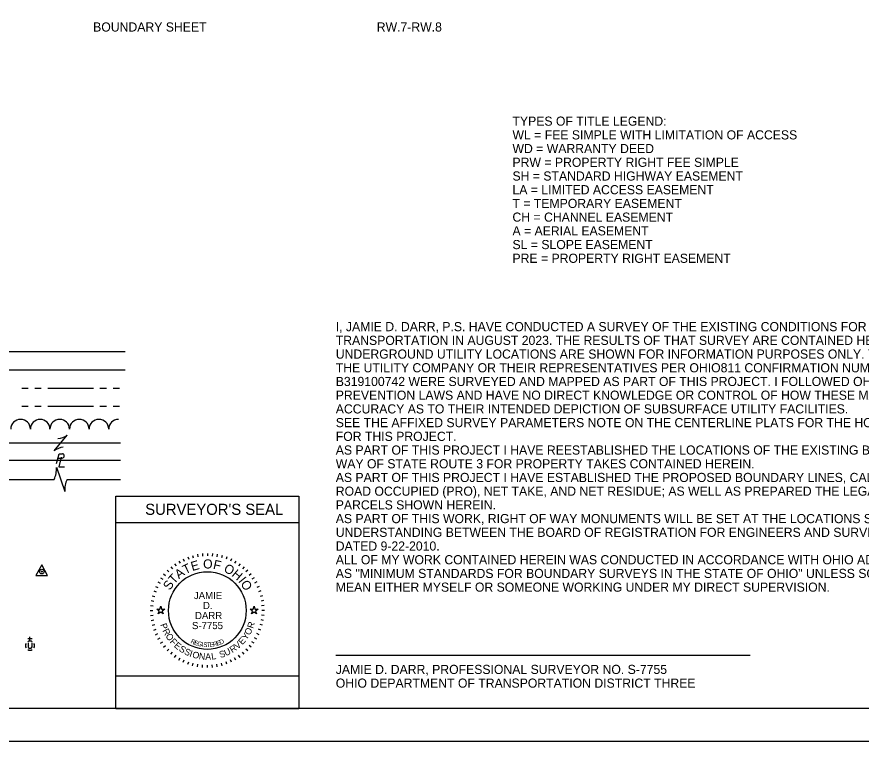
# Model space of a CAD drawing. Extents: x 0 to 34, y 0 to 22.
# Drawn here: x 12.52 to 25.46, y 0 to 11.09 of the extents above; entities that cross this region are included whole.
import ezdxf

# ---------------------------------------------------------------- set-up
doc = ezdxf.new("R2010")
doc.units = 0
for name, color, linetype in [('Default', 7, 'Continuous'), ('SH_Border', 7, 'Continuous'), ('SH_Cut_Line', 7, 'Continuous'), ('SH_Data', 7, 'Continuous'), ('SH_Text', 7, 'Continuous')]:
    doc.layers.add(name, color=color, linetype=linetype)

msp = doc.modelspace()

# ---------------------------------------------------------------- linework, layer by layer
at = {"layer": 'Default'}
msp.add_line((17.41, 1.318), (23.762, 1.318), dxfattribs=at)
for points in [[(14.666, 2.02), (14.713, 2.02), (14.727, 2.065), (14.742, 2.02), (14.789, 2.02), (14.751, 1.992), (14.765, 1.948), (14.727, 1.975), (14.689, 1.948), (14.704, 1.992)], [(16.096, 2.02), (16.143, 2.02), (16.157, 2.065), (16.172, 2.02), (16.219, 2.02), (16.181, 1.992), (16.195, 1.948), (16.157, 1.975), (16.119, 1.948), (16.134, 1.992)]]:
    msp.add_lwpolyline(points, close=True, dxfattribs=at)
at = {"layer": 'SH_Border'}
msp.add_lwpolyline([(1.5, 21.5), (33.5, 21.5), (33.5, 0.5), (1.5, 0.5)], close=True, dxfattribs=at)
at = {"layer": 'SH_Cut_Line'}
msp.add_lwpolyline([(0, 0), (34, 0), (34, 22), (0, 22)], close=True, dxfattribs=at)
at = {"layer": 'SH_Data'}
for p, q in [((14.042, 0.5), (14.042, 3.75)), ((14.042, 3.75), (16.842, 3.75)), ((16.842, 3.75), (16.842, 0.5)), ((14.042, 3.35), (16.842, 3.35)), ((15.29, 2.862), (15.297, 2.822)), ((15.366, 2.872), (15.369, 2.832)), ((15.442, 2.875), (15.442, 2.835)), ((15.519, 2.872), (15.515, 2.832)), ((15.594, 2.862), (15.587, 2.822)), ((15.005, 2.758), (15.025, 2.723)), ((15.072, 2.793), (15.089, 2.757)), ((15.143, 2.822), (15.157, 2.785)), ((15.216, 2.845), (15.226, 2.807)), ((15.669, 2.845), (15.658, 2.807)), ((15.742, 2.822), (15.728, 2.785)), ((15.812, 2.793), (15.795, 2.757)), ((15.88, 2.758), (15.86, 2.723)), ((14.824, 2.619), (14.852, 2.59)), ((14.88, 2.67), (14.906, 2.64)), ((14.94, 2.717), (14.963, 2.684)), ((15.944, 2.717), (15.921, 2.684)), ((16.005, 2.67), (15.979, 2.64)), ((16.061, 2.619), (16.033, 2.59)), ((14.725, 2.502), (14.758, 2.479)), ((14.772, 2.562), (14.803, 2.537)), ((16.113, 2.562), (16.082, 2.537)), ((16.159, 2.502), (16.126, 2.479)), ((14.649, 2.37), (14.685, 2.353)), ((14.684, 2.438), (14.719, 2.418)), ((16.2, 2.438), (16.165, 2.418)), ((16.235, 2.37), (16.199, 2.353)), ((14.597, 2.226), (14.636, 2.216)), ((14.62, 2.299), (14.658, 2.286)), ((16.264, 2.299), (16.227, 2.286)), ((16.287, 2.226), (16.249, 2.216)), ((14.571, 2.076), (14.61, 2.073)), ((14.581, 2.152), (14.62, 2.145)), ((16.304, 2.152), (16.265, 2.145)), ((16.314, 2.076), (16.274, 2.073)), ((14.567, 2), (14.607, 2)), ((16.317, 2), (16.277, 2)), ((14.571, 1.924), (14.61, 1.927)), ((14.581, 1.848), (14.62, 1.855)), ((16.304, 1.848), (16.265, 1.855)), ((16.314, 1.924), (16.274, 1.927)), ((14.597, 1.774), (14.636, 1.784)), ((14.62, 1.701), (14.658, 1.714)), ((16.264, 1.701), (16.227, 1.714)), ((16.287, 1.774), (16.249, 1.784)), ((14.649, 1.63), (14.685, 1.647)), ((14.684, 1.563), (14.719, 1.583)), ((16.2, 1.563), (16.165, 1.583)), ((16.235, 1.63), (16.199, 1.647)), ((14.725, 1.498), (14.758, 1.521)), ((14.772, 1.438), (14.803, 1.463)), ((16.113, 1.438), (16.082, 1.463)), ((16.159, 1.498), (16.126, 1.521)), ((14.824, 1.381), (14.852, 1.41)), ((14.88, 1.33), (14.906, 1.36)), ((14.94, 1.283), (14.963, 1.316)), ((15.944, 1.283), (15.921, 1.316)), ((16.005, 1.33), (15.979, 1.36)), ((16.061, 1.381), (16.033, 1.41)), ((15.005, 1.242), (15.025, 1.277)), ((15.072, 1.207), (15.089, 1.243)), ((15.143, 1.178), (15.157, 1.215)), ((15.216, 1.155), (15.226, 1.193)), ((15.29, 1.138), (15.297, 1.178)), ((15.366, 1.128), (15.369, 1.168)), ((15.442, 1.125), (15.442, 1.165)), ((15.519, 1.128), (15.515, 1.168)), ((15.594, 1.138), (15.587, 1.178)), ((15.669, 1.155), (15.658, 1.193)), ((15.742, 1.178), (15.728, 1.215)), ((15.812, 1.207), (15.795, 1.243)), ((15.88, 1.242), (15.86, 1.277)), ((14.042, 0.5), (16.842, 0.5))]:
    msp.add_line(p, q, dxfattribs=at)
msp.add_lwpolyline([(14.042, 0.5), (14.042, 1), (16.842, 1), (16.842, 0.5)], close=True, dxfattribs=at)
msp.add_circle((15.442, 2), 0.595, dxfattribs=at)
at = {"layer": 'SH_Text'}
for p, q in [((10.698, 5.968), (14.181, 5.968)), ((10.698, 5.688), (14.181, 5.688)), ((12.597, 5.408), (12.697, 5.408)), ((12.797, 5.408), (12.897, 5.408)), ((12.997, 5.408), (13.697, 5.408)), ((13.797, 5.408), (13.897, 5.408)), ((13.997, 5.408), (14.097, 5.408)), ((12.597, 5.128), (12.697, 5.128)), ((12.797, 5.128), (12.897, 5.128)), ((12.997, 5.128), (13.697, 5.128)), ((13.797, 5.128), (13.897, 5.128)), ((13.997, 5.128), (14.097, 5.128)), ((13.093, 4.448), (13.293, 4.688)), ((12.328, 4.568), (14.11, 4.568)), ((13.193, 4.568), (13.193, 4.568)), ((12.328, 4.304), (14.11, 4.304)), ((13.151, 4.333), (13.216, 4.333)), ((13.191, 4.302), (13.191, 4.302)), ((13.128, 4.193), (13.258, 3.824)), ((12.328, 4.008), (13.093, 4.008)), ((13.193, 4.008), (13.193, 4.008)), ((13.293, 4.008), (14.11, 4.008)), ((12.756, 1.564), (12.692, 1.564)), ((12.724, 1.532), (12.724, 1.596)), ((12.697, 1.505), (12.697, 1.436)), ((12.724, 1.462), (12.724, 1.462)), ((12.751, 1.505), (12.751, 1.436))]:
    msp.add_line(p, q, dxfattribs=at)
for points in [[(13.13, 4.254), (13.169, 4.402), (13.22, 4.402)], [(13.204, 4.35), (13.165, 4.202), (13.252, 4.202)]]:
    msp.add_lwpolyline(points, dxfattribs=at)
msp.add_lwpolyline([(12.815, 2.538), (12.995, 2.538), (12.905, 2.699)], close=True, dxfattribs=at)
for radius in [0.035, 0.008]:
    msp.add_circle((12.905, 2.596), radius, dxfattribs=at)
for centre, radius, start, end in [((12.58, 4.778), 0.15, 0.0098, 179.9926), ((12.88, 4.778), 0.15, 0.0098, 179.9926), ((13.18, 4.778), 0.15, 0.0098, 179.9926), ((13.48, 4.778), 0.15, 0.0098, 179.9926), ((13.78, 4.778), 0.15, 0.0098, 179.9926), ((14.08, 4.778), 0.15, 89.9955, 179.9926), ((13.135, 4.903), 0.267, 273.6945, 306.337), ((13.251, 4.233), 0.267, 93.6945, 126.337), ((13.215, 4.368), 0.0345, 270.471, 81.3281), ((12.796, 4.16), 0.334, 332.9422, 5.5848), ((13.59, 3.857), 0.334, 152.9422, 185.5848), ((12.724, 1.462), 0.07, 150.0184, 209.9816), ((12.724, 1.462), 0.07, 60.0184, 120.0157), ((12.724, 1.449), 0.03, 205.1924, 334.8076), ((12.724, 1.462), 0.07, 330.0184, 29.9816), ((12.724, 1.462), 0.07, 239.9843, 299.9816)]:
    msp.add_arc(centre, radius, start, end, dxfattribs=at)

# ---------------------------------------------------------------- texts
at = {"layer": 'Default'}
for s, p in [('I, JAMIE D. DARR, P.S. HAVE CONDUCTED A SURVEY OF THE EXISTING CONDITIONS FOR THE OHIO DEPARTMENT OF', (17.41, 6.278)), ('TRANSPORTATION IN AUGUST 2023. THE RESULTS OF THAT SURVEY ARE CONTAINED HEREIN.', (17.41, 6.068)), ('UNDERGROUND UTILITY LOCATIONS ARE SHOWN FOR INFORMATION PURPOSES ONLY. THEIR LOCATION AS MARKED ON THE GROUND BY ', (17.41, 5.858)), ('THE UTILITY COMPANY OR THEIR REPRESENTATIVES PER OHIO811 CONFIRMATION NUMBERS B319100751-00B,B319100756-00B AND', (17.41, 5.648)), ('B319100742 WERE SURVEYED AND MAPPED AS PART OF THIS PROJECT. I FOLLOWED OHIO811 UTILITY DAMAGE', (17.41, 5.438)), ('PREVENTION LAWS AND HAVE NO DIRECT KNOWLEDGE OR CONTROL OF HOW THESE MARKS WERE PLACED, NOR KNOWLEDGE OF THE ', (17.41, 5.228)), ('ACCURACY AS TO THEIR INTENDED DEPICTION OF SUBSURFACE UTILITY FACILITIES.', (17.41, 5.018)), ('SEE THE AFFIXED SURVEY PARAMETERS NOTE ON THE CENTERLINE PLATS FOR THE HORIZONTAL AND VERTICAL SURVEY PARAMETERS USED ', (17.41, 4.808)), ('FOR THIS PROJECT.', (17.41, 4.598)), ('AS PART OF THIS PROJECT I HAVE REESTABLISHED THE LOCATIONS OF THE EXISTING BOUNDARY LINES AND CENTERLINE OF EXISTING RIGHT OF ', (17.41, 4.388)), ('WAY OF STATE ROUTE 3 FOR PROPERTY TAKES CONTAINED HEREIN.', (17.41, 4.178)), ('AS PART OF THIS PROJECT I HAVE ESTABLISHED THE PROPOSED BOUNDARY LINES, CALCULATED THE GROSS TAKE, PRESENT', (17.41, 3.968)), ('ROAD OCCUPIED (PRO), NET TAKE, AND NET RESIDUE; AS WELL AS PREPARED THE LEGAL DESCRIPTIONS NECESSARY TO ACQUIRE THE', (17.41, 3.758)), ('PARCELS SHOWN HEREIN.', (17.41, 3.548)), ('AS PART OF THIS WORK, RIGHT OF WAY MONUMENTS WILL BE SET AT THE LOCATIONS SHOWN HEREIN PER THE MEMORANDUM OF ', (17.41, 3.338)), ('UNDERSTANDING BETWEEN THE BOARD OF REGISTRATION FOR ENGINEERS AND SURVEYORS AND THE OHIO DEPARTMENT OF TRANSPORTATION ', (17.41, 3.128)), ('DATED 9-22-2010.', (17.41, 2.918)), ('ALL OF MY WORK CONTAINED HEREIN WAS CONDUCTED IN ACCORDANCE WITH OHIO ADMINISTRATIVE CODE 4733-37 COMMONLY KNOWN', (17.41, 2.708)), ('AS "MINIMUM STANDARDS FOR BOUNDARY SURVEYS IN THE STATE OF OHIO" UNLESS SO NOTED. THE WORDS I AND MY AS USED HEREIN ARE TO', (17.41, 2.498)), ('MEAN EITHER MYSELF OR SOMEONE WORKING UNDER MY DIRECT SUPERVISION.', (17.41, 2.288)), ('JAMIE D. DARR, PROFESSIONAL SURVEYOR NO. S-7755                                                               ', (17.41, 1.028)), ('OHIO DEPARTMENT OF TRANSPORTATION DISTRICT THREE', (17.41, 0.818))]:
    msp.add_text(s, height=0.14, dxfattribs=at).set_placement(p)
at = {"layer": 'SH_Data'}
for s, height, p in [('BOUNDARY SHEET                     ', 0.14, (13.692, 10.867)), ('RW.7-RW.8 ', 0.14, (18.038, 10.867)), ("SURVEYOR'S SEAL", 0.17, (14.49, 3.465)), ('JAMIE', 0.11, (15.236, 2.175)), ('D.', 0.11, (15.375, 2.022)), ('DARR', 0.11, (15.253, 1.868)), ('S-7755', 0.11, (15.207, 1.715))]:
    msp.add_text(s, height=height, dxfattribs=at).set_placement(p)
for s, height, rotation, p in [('T', 0.14, 25.7167, (15.104, 2.552)), ('E', 0.14, 15.7571, (15.211, 2.604)), ('O', 0.14, 359.7812, (15.377, 2.644)), ('F', 0.14, 347.4362, (15.523, 2.642)), ('A', 0.14, 36.4747, (15.006, 2.478)), ('O', 0.14, 332.2586, (15.682, 2.602)), ('H', 0.14, 319.9136, (15.805, 2.536)), ('S', 0.14, 57.1924, (14.87, 2.301)), ('T', 0.14, 46.4344, (14.931, 2.396)), ('I', 0.14, 308.367, (15.909, 2.448)), ('O', 0.14, 303.1491, (15.944, 2.409)), ('R', 0.1, 70.983, (16.143, 1.717)), ('P', 0.1, 289.7431, (14.718, 1.784)), ('R', 0.1, 296.9802, (14.752, 1.693)), ('O', 0.1, 62.7428, (16.092, 1.613)), ('O', 0.1, 304.7158, (14.795, 1.608)), ('F', 0.1, 312.956, (14.861, 1.516)), ('R', 0.07, 334.487, (15.18, 1.505)), ('D', 0.07, 23.3052, (15.643, 1.477)), ('E', 0.1, 48.2687, (15.979, 1.467)), ('Y', 0.1, 55.5058, (16.042, 1.54)), ('E', 0.1, 319.6885, (14.923, 1.45)), ('S', 0.1, 326.9255, (14.998, 1.389)), ('E', 0.07, 341.04, (15.233, 1.48)), ('G', 0.07, 347.4752, (15.284, 1.462)), ('I', 0.07, 353.7858, (15.351, 1.447)), ('S', 0.07, 356.8926, (15.378, 1.443)), ('T', 0.07, 3.0061, (15.428, 1.439)), ('E', 0.07, 6.0117, (15.481, 1.441)), ('R', 0.07, 11.9184, (15.535, 1.447)), ('E', 0.07, 17.6836, (15.592, 1.46)), ('U', 0.1, 25.5604, (15.726, 1.299)), ('R', 0.1, 33.296, (15.824, 1.347)), ('V', 0.1, 41.0316, (15.904, 1.401)), ('S', 0.1, 334.1626, (15.078, 1.337)), ('I', 0.1, 341.3997, (15.161, 1.298)), ('O', 0.1, 345.1351, (15.204, 1.282)), ('N', 0.1, 353.3752, (15.308, 1.255)), ('A', 0.1, 1.1108, (15.411, 1.244)), ('L', 0.1, 8.3479, (15.509, 1.247)), ('S', 0.1, 18.3234, (15.643, 1.271))]:
    msp.add_text(s, height=height, rotation=rotation, dxfattribs=at).set_placement(p)
at = {"layer": 'SH_Text'}
for s, p in [('TYPES OF TITLE LEGEND:', (20.118, 9.425)), ('WL = FEE SIMPLE WITH LIMITATION OF ACCESS', (20.118, 9.215)), ('WD = WARRANTY DEED', (20.118, 9.005)), ('PRW = PROPERTY RIGHT FEE SIMPLE', (20.118, 8.795)), ('SH = STANDARD HIGHWAY EASEMENT', (20.118, 8.585)), ('LA = LIMITED ACCESS EASEMENT', (20.118, 8.375)), ('T = TEMPORARY EASEMENT', (20.118, 8.165)), ('CH = CHANNEL EASEMENT', (20.118, 7.955)), ('A = AERIAL EASEMENT', (20.118, 7.745)), ('SL = SLOPE EASEMENT', (20.118, 7.535)), ('PRE = PROPERTY RIGHT EASEMENT', (20.118, 7.325))]:
    msp.add_text(s, height=0.14, dxfattribs=at).set_placement(p)

doc.saveas('drawing.dxf')
